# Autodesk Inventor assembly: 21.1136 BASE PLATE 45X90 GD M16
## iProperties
Created: 2007-03
Part Number: 21.1136 BASE PLATE 45X90 GD M16
Document SubType Name: Assembly
Designer: Andy Moles
Author: Andy Moles
